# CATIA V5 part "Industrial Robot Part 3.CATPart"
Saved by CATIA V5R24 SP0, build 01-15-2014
Part number: Industrial Robot Part 3
Material "Light Beige": density 7860 kg/m3, Young's modulus 2e+11 Pa, Poisson ratio 0.266
Bounding box of the stored display mesh (mm): x -204.036 to 159.297, y -395.005 to 79.965, z -76.666 to 354.043
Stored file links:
  C:\Users\cdl\Downloads\2024_CAD_final\p2\Industrial Robot Part 3.CATPart
  D:\Program Files\Dassault Systemes\B24\win_b64\startup\materials\Catalog.CATMaterial
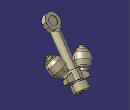
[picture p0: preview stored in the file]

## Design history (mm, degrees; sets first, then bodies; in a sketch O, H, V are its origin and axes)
Set1 "Reference Datas"
  Plane1 "Middle Plane": type Offset, RefPlane Plane2, Offset 0
  Plane2 "Middle Plane": stored without definition
Body1 (main body), material "Light Beige"
  Body2 "Solid 1"
    Solid1: solid without history
  Assemble1: tool Body2
  Body3 "Solid 2"
    Solid2 "Solid.1": solid without history
  Assemble2: tool Body3
  Translate1: Direction (0, 0, 1), Length -650, ToTransfor Assemble2
  Translate2: Direction (0, 1, 0), Length 224, ToTransfor Translate1
  Translate3: Direction (0, 1, 0), Length 20, ToTransfor Translate2
  Rotate1: Axis Z axis, ToTransfor Translate3, Angle 48
  Rotate2: Axis Y axis, ToTransfor Rotate1, Angle 85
